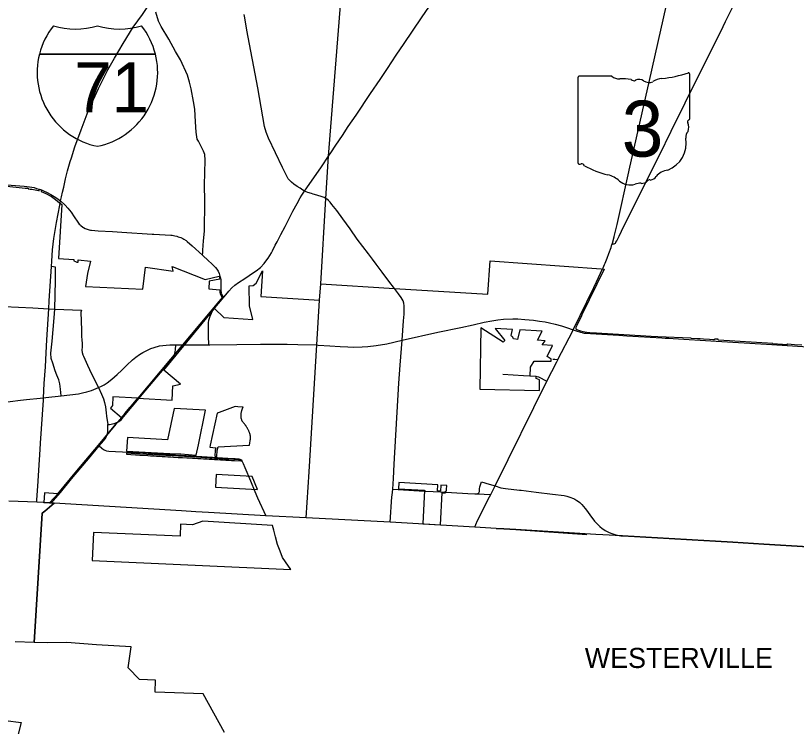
# Model space of a CAD drawing. Extents: x 1729596 to 1925846, y 659247 to 911751.
# Drawn here: x 1836127 to 1855559, y 772373 to 790063 of the extents above; entities that cross this region are included whole.
import ezdxf

# ---------------------------------------------------------------- set-up
doc = ezdxf.new("R2010")
doc.units = 0
for name, color, linetype in [('GM_X_City_Street', 7, 'Continuous'), ('GM_X_Corporation', 7, 'Continuous'), ('GM_X_Corporation_Text', 7, 'Continuous'), ('GM_X_County', 7, 'Continuous'), ('GM_X_County_Road', 7, 'Continuous'), ('GM_X_Interstate_Route', 7, 'Continuous'), ('GM_X_Interstate_Shield', 7, 'Continuous'), ('GM_X_State_Route', 7, 'Continuous'), ('GM_X_State_Shield', 7, 'Continuous'), ('GM_X_Township', 7, 'Continuous'), ('GM_X_Township_Road', 7, 'Continuous')]:
    doc.layers.add(name, color=color, linetype=linetype)

msp = doc.modelspace()

# ---------------------------------------------------------------- linework, layer by layer
at = {"layer": 'GM_X_City_Street'}
for points in [[(1845795, 782632), (1845801, 782714), (1845799, 782843), (1845789, 782905), (1845769, 782961), (1845719, 783045), (1845654, 783136), (1845556, 783268), (1845531, 783302)], [(1835705, 782831), (1835839, 782824), (1836553, 782786), (1836955, 782764), (1837100, 782758), (1837765, 782732)], [(1837765, 782732), (1837753, 782682), (1837765, 782232), (1837770, 782095)], [(1840933, 781871), (1840926, 782090), (1840925, 782331), (1840928, 782415), (1840938, 782483), (1840967, 782584), (1840998, 782659), (1841047, 782741), (1841072, 782775)], [(1845750, 781984), (1845750, 781984), (1845784, 782465), (1845795, 782632)], [(1845750, 781984), (1846636, 782185), (1847206, 782302), (1847513, 782368), (1847786, 782434), (1847977, 782469), (1848131, 782490), (1848273, 782507), (1848502, 782514), (1848624, 782515), (1848801, 782501), (1849017, 782481), (1849162, 782462), (1849304, 782438), (1849411, 782418), (1849555, 782383), (1849710, 782340), (1849838, 782298), (1850003, 782242)], [(1850003, 782242), (1850074, 782221), (1850183, 782185), (1850228, 782173), (1850245, 782170), (1850281, 782163), (1850312, 782159), (1850325, 782158), (1850431, 782150), (1850574, 782141), (1851143, 782107), (1851335, 782095)], [(1837770, 782095), (1837775, 781981), (1837783, 781922), (1837779, 781819), (1837777, 781733), (1837782, 781676), (1837802, 781618), (1837814, 781583), (1837912, 781362), (1838015, 781147), (1838193, 780805)], [(1843653, 781863), (1843947, 781841), (1844201, 781827), (1844395, 781817), (1844535, 781814), (1844750, 781817), (1844893, 781827), (1845099, 781849), (1845367, 781896), (1845750, 781984)], [(1845701, 781367), (1845750, 781984)], [(1851335, 782095), (1852214, 782040)], [(1852214, 782040), (1852297, 782035), (1852381, 782031), (1852490, 782023), (1853564, 781958), (1854813, 781882), (1856233, 781796), (1856759, 781767), (1857122, 781742)], [(1837262, 780598), (1837472, 780623), (1837692, 780652), (1837788, 780671), (1837899, 780697), (1838012, 780736), (1838193, 780805), (1838267, 780838), (1838327, 780874), (1838407, 780927), (1838522, 781011), (1838653, 781132), (1838768, 781235), (1838897, 781361), (1839033, 781492), (1839117, 781565), (1839207, 781627), (1839292, 781682), (1839379, 781723), (1839494, 781774), (1839571, 781804), (1839711, 781841), (1839792, 781854), (1839873, 781862), (1839966, 781866), (1840114, 781870)], [(1840090, 781659), (1840100, 781698), (1840105, 781743), (1840114, 781870)], [(1840114, 781870), (1840114, 781870), (1840273, 781870)], [(1840378, 781870), (1840933, 781871), (1840960, 781871)], [(1840960, 781871), (1841634, 781878), (1842225, 781888), (1842619, 781888), (1842884, 781888), (1843152, 781878), (1843626, 781866), (1843653, 781863)], [(1843361, 777564), (1843430, 778709), (1843626, 781866)], [(1849499, 781514), (1849547, 781511), (1849624, 781505)], [(1845497, 778125), (1845512, 778280), (1845535, 778545), (1845550, 778898), (1845665, 780916), (1845701, 781367)], [(1849078, 781088), (1849139, 781069), (1849352, 780964)], [(1838193, 780805), (1838268, 780643), (1838314, 780527), (1838341, 780436), (1838361, 780322), (1838379, 780175), (1838390, 780094), (1838419, 779886)], [(1838675, 779950), (1838679, 779951), (1838721, 779977), (1838758, 780012), (1838814, 780076), (1839202, 780542)], [(1838398, 779616), (1838413, 779659), (1838423, 779716), (1838425, 779769), (1838424, 779828), (1838419, 779886)], [(1838419, 779886), (1838461, 779889), (1838582, 779913), (1838619, 779924), (1838675, 779950)], [(1837662, 778703), (1837938, 779032), (1838207, 779353), (1838312, 779478), (1838354, 779530), (1838378, 779568), (1838391, 779594), (1838398, 779616)], [(1838207, 779353), (1838276, 779296), (1838316, 779268), (1838343, 779249), (1838391, 779233), (1838445, 779226), (1839292, 779180), (1840238, 779123), (1841028, 779074), (1841530, 779043), (1841590, 779040), (1841681, 779032), (1841706, 779026), (1841723, 779017), (1841743, 779001)], [(1841743, 779001), (1841743, 779001), (1841760, 778978), (1841792, 778916), (1841834, 778818), (1841974, 778482)], [(1837011, 777935), (1837067, 777991), (1837241, 778192), (1837519, 778532), (1837662, 778703)], [(1846702, 778207), (1847381, 778168), (1847556, 778157), (1847623, 778159), (1847653, 778187), (1847668, 778222), (1847673, 778281), (1847683, 778338), (1847722, 778457)], [(1847722, 778457), (1847915, 778403), (1848062, 778361)], [(1845512, 778280), (1846301, 778231), (1846340, 778229)], [(1848062, 778361), (1848204, 778314), (1848323, 778297), (1848668, 778252), (1848705, 778248)], [(1842083, 778219), (1842149, 778061), (1842358, 777614)], [(1845449, 777453), (1845493, 778084), (1845497, 778125)], [(1847623, 778159), (1847953, 778140)], [(1848705, 778248), (1849085, 778201), (1849491, 778152), (1849783, 778117), (1849847, 778104), (1849922, 778081), (1850012, 778044), (1850046, 778026), (1850094, 777998), (1850140, 777966), (1850171, 777942), (1850219, 777897), (1850262, 777849), (1850300, 777796), (1850362, 777718), (1850435, 777616), (1850491, 777539), (1850536, 777481), (1850600, 777410), (1850669, 777346), (1850724, 777300), (1850767, 777270), (1850802, 777249), (1850896, 777202), (1850967, 777174), (1851065, 777144), (1851193, 777116), (1851228, 777114), (1851242, 777113)], [(1848085, 777300), (1848276, 777289), (1848580, 777271), (1850345, 777150)], [(1851242, 777113), (1853977, 776957), (1854746, 776908), (1855849, 776844), (1860837, 776510)]]:
    msp.add_lwpolyline(points, dxfattribs=at)
at = {"layer": 'GM_X_Corporation'}
for points in [[(1835905, 785817), (1836363, 785772), (1836439, 785767), (1836438, 785752), (1836485, 785747), (1836530, 785742), (1836571, 785735), (1836613, 785728), (1836656, 785718), (1836693, 785710), (1836710, 785705), (1836712, 785746), (1836743, 785733), (1836768, 785721), (1836766, 785689), (1836880, 785635), (1837022, 785558), (1837123, 785488), (1837222, 785404), (1837273, 785365), (1837194, 784015), (1837577, 783991), (1837574, 783956), (1837620, 783941), (1837650, 783930), (1837681, 783927), (1837687, 783984), (1837990, 783954), (1837918, 783644), (1837865, 783321), (1839293, 783253), (1839358, 783800), (1840047, 783704), (1840026, 783821), (1840842, 783494), (1841189, 783579), (1841206, 783505), (1840944, 783454), (1840934, 783259), (1841208, 783235), (1841210, 783181), (1841220, 783138), (1841242, 783087), (1841269, 783047), (1841184, 782945), (1840280, 781871), (1839165, 780541), (1838544, 780578), (1838538, 780363), (1838485, 780296), (1838765, 780060), (1838745, 780037), (1838742, 780031), (1838725, 780013), (1838668, 779945), (1838625, 779894), (1838186, 779371), (1837650, 778732), (1837174, 778163), (1836848, 778182), (1836833, 777945), (1836973, 777937), (1837085, 777931), (1836852, 777733), (1836789, 777680), (1836587, 774459), (1836117, 774478)], [(1841326, 772218), (1840796, 773182), (1839597, 773227), (1839608, 773527), (1839213, 773542), (1838929, 773828), (1839006, 774350), (1838141, 774402), (1837403, 774461), (1836916, 774455), (1836587, 774459), (1836789, 777680), (1836852, 777733), (1837085, 777931), (1836973, 777937), (1836974, 777938), (1837086, 778057), (1837174, 778163), (1837650, 778732), (1838186, 779371), (1838625, 779894), (1838668, 779945), (1838725, 780013), (1838742, 780031), (1838745, 780037), (1838765, 780060), (1838767, 780058), (1838846, 780153), (1838843, 780156), (1838968, 780306), (1838971, 780303), (1839170, 780540), (1840019, 780491), (1840040, 780852), (1840233, 780886), (1839815, 781235), (1841073, 782777), (1841309, 782546), (1842031, 782501), (1841945, 782843), (1841941, 783336), (1842037, 783342), (1842114, 783400), (1842268, 783711), (1842228, 783073), (1843694, 782979), (1843719, 783387), (1845556, 783268), (1847880, 783128), (1847941, 783961), (1850704, 783760), (1850771, 783756), (1850223, 782617), (1850199, 782567), (1850139, 782444), (1850095, 782354), (1850085, 782333), (1850074, 782313), (1850069, 782299), (1850068, 782279), (1850071, 782269), (1850095, 782252), (1850134, 782235), (1850187, 782215), (1850218, 782207), (1850250, 782200), (1850345, 782187), (1850498, 782169), (1850510, 782168), (1850585, 782164), (1851810, 782096), (1851944, 782088), (1852113, 782080), (1852935, 782042), (1852934, 782037), (1853098, 782027), (1853168, 782023), (1853247, 782018), (1853247, 782016), (1853395, 782006), (1853479, 782000), (1853492, 781999), (1853509, 781998), (1853511, 781998), (1853514, 781999), (1853517, 782000), (1853519, 782001), (1853521, 782002), (1853522, 782003), (1853524, 782005), (1853526, 782007), (1853527, 782010), (1853528, 782013), (1853529, 782016), (1853529, 782020), (1853603, 782018), (1853603, 782011), (1853603, 782008), (1853604, 782004), (1853605, 782001), (1853607, 781999), (1853608, 781997), (1853610, 781995), (1853614, 781993), (1853615, 781992), (1853618, 781992), (1853621, 781991), (1854969, 781911), (1854968, 781901), (1855339, 781880), (1855340, 781890), (1855349, 781890), (1855515, 781881), (1855693, 781873)], [(1835872, 772517), (1836265, 772469), (1836073, 771716)]]:
    msp.add_lwpolyline(points, dxfattribs=at)
for points in [[(1847680, 780763), (1849165, 780736), (1849163, 781002), (1849082, 781034), (1849083, 781084), (1848937, 781088), (1848942, 781314), (1849029, 781462), (1849454, 781459), (1849454, 781517), (1849430, 781526), (1849356, 781577), (1849486, 781850), (1849232, 781869), (1849306, 781970), (1849115, 781988), (1849235, 782207), (1848677, 782244), (1848617, 782001), (1848528, 782020), (1848519, 782020), (1848515, 782021), (1848510, 782031), (1848500, 782057), (1848482, 782077), (1848469, 782087), (1848458, 782099), (1848494, 782247), (1848066, 782273), (1848300, 781976), (1848262, 781937), (1847707, 782296)], [(1838890, 779225), (1839969, 779163), (1839969, 779168), (1840239, 779153), (1840620, 779123), (1840675, 779380), (1840855, 780239), (1840069, 780286), (1839907, 779506), (1838909, 779563)], [(1840970, 779369), (1840959, 779320), (1841110, 779309), (1841096, 779248), (1841087, 779095), (1841138, 779092), (1841146, 779243), (1841165, 779331), (1841942, 779371), (1841944, 779376), (1841948, 779388), (1841951, 779398), (1841955, 779413), (1841955, 779414), (1841958, 779426), (1841959, 779436), (1841960, 779440), (1841966, 779468), (1841967, 779474), (1841967, 779484), (1841968, 779496), (1841968, 779507), (1841969, 779514), (1841970, 779522), (1841971, 779532), (1841971, 779535), (1841971, 779551), (1841970, 779593), (1841970, 779603), (1841968, 779613), (1841966, 779626), (1841964, 779635), (1841962, 779639), (1841955, 779659), (1841950, 779678), (1841946, 779691), (1841939, 779707), (1841934, 779717), (1841932, 779723), (1841928, 779732), (1841922, 779745), (1841916, 779757), (1841900, 779787), (1841897, 779793), (1841890, 779804), (1841884, 779814), (1841866, 779846), (1841864, 779849), (1841859, 779856), (1841855, 779862), (1841851, 779865), (1841847, 779870), (1841844, 779872), (1841835, 779883), (1841831, 779888), (1841820, 779903), (1841814, 779910), (1841809, 779917), (1841798, 779927), (1841797, 779929), (1841790, 779938), (1841782, 779950), (1841776, 779959), (1841773, 779964), (1841771, 779969), (1841769, 779972), (1841768, 779975), (1841761, 779987), (1841759, 779993), (1841756, 780002), (1841754, 780006), (1841749, 780017), (1841747, 780021), (1841745, 780025), (1841745, 780027), (1841742, 780036), (1841742, 780044), (1841740, 780055), (1841740, 780061), (1841740, 780063), (1841740, 780070), (1841738, 780090), (1841738, 780093), (1841738, 780099), (1841739, 780112), (1841740, 780136), (1841740, 780140), (1841741, 780150), (1841743, 780164), (1841744, 780176), (1841748, 780194), (1841749, 780200), (1841752, 780208), (1841752, 780210), (1841756, 780227), (1841761, 780247), (1841762, 780250), (1841764, 780257), (1841766, 780263), (1841768, 780271), (1841770, 780276), (1841772, 780283), (1841774, 780288), (1841777, 780293), (1841779, 780298), (1841783, 780304), (1841785, 780307), (1841788, 780313), (1841789, 780316), (1841792, 780320), (1841659, 780327), (1841589, 780331), (1841190, 780184), (1841140, 780165)], [(1838888, 779170), (1838887, 779146), (1839222, 779126), (1839417, 779112), (1839487, 779108), (1839562, 779104), (1839637, 779100), (1839707, 779096), (1839777, 779092), (1839847, 779088), (1839917, 779084), (1839987, 779080), (1840057, 779076), (1840172, 779069), (1840174, 779069), (1840277, 779063), (1840280, 779063), (1840386, 779057), (1840456, 779053), (1840526, 779049), (1840595, 779045), (1840665, 779041), (1840735, 779037), (1840805, 779033), (1840874, 779029), (1840944, 779025), (1841014, 779021), (1841079, 779018), (1841081, 779017), (1841083, 779017), (1841153, 779013), (1841156, 779013), (1841158, 779013), (1841223, 779009), (1841292, 779006), (1841362, 779002), (1841432, 778998), (1841501, 778994), (1841571, 778990), (1841732, 778980), (1841765, 778979), (1841755, 779000), (1841675, 779005), (1841439, 779020), (1841311, 779027), (1841080, 779042), (1840617, 779071), (1840183, 779097), (1839224, 779152)], [(1841118, 778645), (1841099, 778328), (1842145, 778266), (1842016, 778588)], [(1846859, 778368), (1846710, 778378), (1846702, 778229), (1846625, 778234), (1846634, 778383), (1845663, 778439), (1845654, 778289), (1846303, 778254), (1846258, 777411), (1846699, 777386), (1846740, 778185), (1846816, 778181), (1846819, 778221), (1846824, 778221), (1846830, 778222), (1846834, 778223), (1846838, 778226), (1846842, 778229), (1846846, 778234), (1846848, 778239), (1846850, 778244), (1846851, 778248), (1846852, 778267)], [(1838033, 776502), (1842974, 776280), (1842842, 776467), (1842767, 776576), (1842710, 776732), (1842648, 776896), (1842594, 777087), (1842556, 777259), (1842523, 777374), (1840783, 777481), (1840533, 777392), (1840233, 777406), (1840220, 777106), (1838064, 777201)]]:
    msp.add_lwpolyline(points, close=True, dxfattribs=at)
at = {"layer": 'GM_X_County'}
msp.add_lwpolyline([(1855849, 776844), (1854746, 776908), (1853977, 776957), (1851228, 777114), (1851193, 777116), (1850903, 777132), (1850744, 777141), (1850569, 777151), (1848580, 777271), (1848276, 777289), (1848085, 777300), (1847560, 777333), (1845449, 777453), (1843361, 777564), (1842358, 777614), (1840924, 777694), (1840611, 777712), (1840257, 777736), (1837085, 777931), (1837011, 777935), (1836973, 777937), (1836651, 777955), (1835956, 777979)], dxfattribs=at)
at = {"layer": 'GM_X_County_Road'}
for points in [[(1851209, 784694), (1851326, 784936), (1852148, 786590), (1852443, 787187), (1853141, 788601), (1853675, 789667), (1853798, 789914), (1853979, 790280), (1854272, 790859), (1854392, 791103), (1854649, 791581), (1855260, 792799), (1855898, 794041), (1856273, 794777), (1856673, 795566), (1856869, 795971), (1857028, 796294)], [(1843969, 786645), (1844100, 786841), (1844260, 787083), (1844407, 787305), (1844600, 787588), (1844962, 788122), (1845200, 788475), (1845400, 788775), (1845475, 788889), (1845613, 789100), (1845780, 789348), (1846245, 790032), (1846408, 790272)], [(1843318, 785694), (1843279, 785722), (1843205, 785766), (1843131, 785811), (1843049, 785869), (1842990, 785919), (1842913, 786003), (1842770, 786283), (1842422, 787009), (1842359, 787165), (1842321, 787304), (1842151, 788263), (1841879, 789699), (1841828, 790004), (1841819, 790093)], [(1842589, 784346), (1842634, 784434), (1842728, 784617), (1842832, 784814), (1843028, 785192), (1843132, 785389), (1843208, 785531), (1843250, 785597), (1843318, 785694), (1843374, 785774), (1843742, 786301), (1843918, 786568), (1843969, 786645)], [(1830137, 786102), (1830408, 786127), (1830473, 786131), (1830595, 786143), (1830674, 786150), (1830727, 786150), (1830805, 786149), (1831205, 786125), (1831840, 786089), (1832575, 786043), (1833895, 785967), (1834638, 785924), (1835200, 785890), (1836012, 785840), (1836343, 785821), (1836473, 785802), (1836589, 785781), (1836648, 785764), (1836710, 785745), (1836767, 785724)], [(1836767, 785724), (1836786, 785717), (1836824, 785700)], [(1836824, 785700), (1836909, 785663), (1837004, 785613), (1837124, 785539), (1837243, 785449), (1837357, 785344), (1837425, 785273), (1837506, 785171), (1837585, 785055), (1837672, 784921), (1837711, 784875), (1837731, 784855), (1837753, 784836), (1837800, 784801), (1837815, 784791), (1837856, 784768), (1837907, 784747), (1837933, 784738), (1837960, 784731), (1837988, 784725), (1838015, 784721), (1838179, 784709), (1838542, 784687), (1838768, 784673), (1839525, 784627), (1839566, 784625), (1839988, 784599), (1840024, 784595), (1840057, 784590), (1840091, 784584), (1840142, 784571), (1840175, 784561), (1840207, 784550), (1840239, 784537), (1840288, 784514), (1840316, 784498), (1840369, 784463), (1840394, 784443), (1840518, 784334), (1840776, 784103), (1840930, 783961), (1841001, 783894), (1841068, 783830), (1841103, 783792), (1841135, 783749), (1841164, 783700), (1841192, 783642), (1841213, 783581), (1841227, 783525), (1841231, 783496), (1841234, 783467), (1841236, 783438), (1841235, 783218), (1841240, 783168), (1841245, 783146), (1841249, 783135), (1841259, 783112), (1841275, 783087), (1841308, 783054)], [(1843915, 785461), (1843910, 785466), (1843876, 785495), (1843850, 785510), (1843805, 785538), (1843756, 785553), (1843625, 785594), (1843533, 785620), (1843488, 785634), (1843403, 785662), (1843358, 785678), (1843318, 785694)], [(1845531, 783302), (1845441, 783422), (1845252, 783676), (1845103, 783878), (1845012, 784005), (1844911, 784131), (1844769, 784320), (1844631, 784501), (1844451, 784757), (1844268, 785009), (1844121, 785212), (1843999, 785361), (1843954, 785418), (1843915, 785461)], [(1850968, 784364), (1851009, 784379), (1851023, 784383), (1851040, 784392), (1851054, 784403), (1851062, 784412), (1851069, 784422), (1851092, 784460), (1851118, 784507), (1851150, 784573), (1851209, 784694)], [(1842518, 784205), (1842589, 784346)], [(1841308, 783054), (1841360, 783114), (1841434, 783206), (1841511, 783291), (1841584, 783354), (1841672, 783417), (1841829, 783524), (1842048, 783668), (1842113, 783713), (1842218, 783797), (1842316, 783897), (1842383, 783983), (1842415, 784029), (1842495, 784159), (1842518, 784205)], [(1841072, 782775), (1841086, 782794), (1841225, 782955), (1841308, 783054)], [(1840273, 781870), (1840318, 781870), (1840378, 781870)], [(1840053, 781560), (1840062, 781581), (1840072, 781607), (1840088, 781652), (1840090, 781659)], [(1839781, 781234), (1839795, 781251), (1839953, 781436), (1840049, 781552), (1840053, 781560)], [(1839202, 780542), (1839276, 780630), (1839733, 781176), (1839781, 781234)]]:
    msp.add_lwpolyline(points, dxfattribs=at)
at = {"layer": 'GM_X_Interstate_Route'}
for points in [[(1837487, 786429), (1837514, 786520), (1837601, 786793), (1837756, 787221), (1837932, 787687), (1838187, 788245), (1838424, 788716), (1838589, 789007), (1838800, 789367), (1839053, 789775), (1839282, 790094), (1839487, 790389), (1839554, 790475), (1839800, 790800), (1840096, 791202), (1840599, 791880), (1841473, 793063), (1842402, 794310), (1842953, 795035), (1844609, 797255), (1845106, 797922), (1845407, 798332)], [(1837267, 785553), (1837294, 785668), (1837323, 785796), (1837371, 786001), (1837421, 786203), (1837487, 786429)], [(1837223, 785347), (1837233, 785398), (1837243, 785449), (1837267, 785553)], [(1837020, 783821), (1837027, 783953), (1837045, 784237), (1837075, 784514), (1837141, 784917), (1837223, 785347)], [(1836817, 780494), (1836820, 780550), (1836840, 780909), (1836868, 781322), (1836890, 781668), (1836906, 781995), (1836955, 782764), (1836962, 782965), (1837020, 783821)], [(1836705, 778752), (1836739, 779265), (1836749, 779422), (1836817, 780494)], [(1836655, 778007), (1836686, 778478), (1836705, 778752)], [(1836651, 777955), (1836655, 778007)]]:
    msp.add_lwpolyline(points, dxfattribs=at)
at = {"layer": 'GM_X_Interstate_Shield'}
for p, q in [((1836721, 789106), (1839606, 789106)), ((1839606, 789106), (1836721, 789106)), ((1839606, 789106), (1836721, 789106)), ((1836721, 789106), (1839606, 789106)), ((1839606, 789106), (1836721, 789106)), ((1839606, 789106), (1836721, 789106))]:
    msp.add_line(p, q, dxfattribs=at)
for centre, start, end in [((1838538, 788647), 141.669, 165.8066), ((1838538, 788647), 141.669, 165.8066), ((1837615, 791603), 253.0091, 286.9909), ((1837615, 791603), 253.0091, 286.9909), ((1838711, 791603), 253.0091, 286.9909), ((1838711, 791603), 253.0091, 286.9909), ((1837788, 788647), 14.1934, 38.331), ((1837788, 788647), 14.1934, 38.331), ((1838538, 788647), 165.8066, 258.463), ((1838538, 788647), 165.8066, 258.463), ((1837788, 788647), 281.537, 14.1934), ((1837788, 788647), 281.537, 14.1934)]:
    msp.add_arc(centre, 1875, start, end, dxfattribs=at)
at = {"layer": 'GM_X_State_Route'}
for points in [[(1851027, 784561), (1851027, 784562), (1851101, 784861), (1851390, 786171), (1851399, 786214), (1851899, 788445), (1852470, 790966), (1852613, 791609), (1852746, 792202), (1852871, 792760), (1853072, 793659), (1853214, 794287), (1853225, 794338)], [(1850785, 783867), (1850801, 783904), (1850850, 784024), (1850893, 784139), (1850946, 784292), (1850968, 784364), (1850980, 784401), (1851027, 784561)], [(1837100, 782758), (1837122, 783468), (1837121, 783747), (1837119, 783802), (1837020, 783821)], [(1850584, 783434), (1850737, 783758), (1850741, 783767), (1850750, 783788), (1850785, 783867)], [(1850003, 782242), (1850516, 783296), (1850578, 783422), (1850584, 783434)], [(1837005, 781660), (1837033, 781960), (1837087, 782544), (1837100, 782758)], [(1849593, 781442), (1849619, 781493), (1849624, 781505), (1849991, 782220), (1850003, 782242)], [(1837262, 780598), (1837243, 780763), (1837224, 780898), (1837199, 780995), (1837156, 781115), (1837115, 781226), (1837051, 781415), (1837014, 781532), (1837005, 781660)], [(1847923, 778082), (1847953, 778140), (1848062, 778361), (1849352, 780964), (1849593, 781442)], [(1836397, 780507), (1836740, 780542), (1836820, 780550), (1836877, 780557), (1837262, 780598)], [(1835722, 780425), (1836249, 780492), (1836397, 780507)], [(1847560, 777333), (1847581, 777396), (1847623, 777500), (1847923, 778082)]]:
    msp.add_lwpolyline(points, dxfattribs=at)
at = {"layer": 'GM_X_State_Shield'}
for p, q in [((1852904, 787501), (1852904, 788607)), ((1852904, 787501), (1852904, 788607)), ((1850120, 788518), (1850120, 786405)), ((1850120, 788518), (1850120, 786405)), ((1850963, 788554), (1850147, 788554)), ((1850963, 788554), (1850147, 788554)), ((1852904, 787501), (1852904, 787501)), ((1852904, 787501), (1852904, 787501))]:
    msp.add_line(p, q, dxfattribs=at)
for centre, radius, start, end in [((1851913, 791435), 2953, 275.8445, 288.9065), ((1851913, 791435), 2953, 275.8445, 288.9065), ((1852873, 788611), 31, 351.8621, 97.738), ((1852873, 788611), 31, 351.8621, 97.738), ((1850152, 788522), 32.3, 98.1301, 188.1301), ((1850152, 788522), 32.3, 98.1301, 188.1301), ((1851157, 788800), 313, 231.6195, 271.1119), ((1851157, 788800), 313, 231.6195, 271.1119), ((1851261, 787368), 1123, 80.4867, 94.9883), ((1851261, 787368), 1123, 80.4867, 94.9883), ((1851516, 788533), 90.3, 219.7921, 297.1024), ((1851516, 788533), 90.3, 219.7921, 297.1024), ((1851648, 788289), 188, 54.4667, 119.1411), ((1851648, 788289), 188, 54.4667, 119.1411), ((1851890, 788624), 226, 233.8562, 294.8282), ((1851890, 788624), 226, 233.8562, 294.8282), ((1852289, 787909), 594, 97.3462, 120.7689), ((1852289, 787909), 594, 97.3462, 120.7689), ((1852897, 787420), 48, 107.944, 210.337), ((1852897, 787420), 48, 107.944, 210.337), ((1852592, 787280), 288, 340.033, 23.6496), ((1852592, 787280), 288, 340.033, 23.6496), ((1852871, 787497), 33.2, 289.6038, 7.7341), ((1852871, 787497), 33.2, 289.6038, 7.7341), ((1852078, 786898), 739, 292.3089, 8.9858), ((1852078, 786898), 739, 292.3089, 8.9858), ((1853015, 787039), 210, 136.8065, 186.9296), ((1853015, 787039), 210, 136.8065, 186.9296), ((1850152, 786400), 32.5, 171.9584, 258.3066), ((1850152, 786400), 32.5, 171.9584, 258.3066), ((1850157, 786616), 248, 267.339, 280.6039), ((1850157, 786616), 248, 267.339, 280.6039), ((1850208, 786283), 89.5, 29.7484, 93.2717), ((1850208, 786283), 89.5, 29.7484, 93.2717), ((1851338, 788181), 2132, 240.4129, 257.1985), ((1851338, 788181), 2132, 240.4129, 257.1985), ((1850703, 785455), 667, 47.1842, 75.836), ((1850703, 785455), 667, 47.1842, 75.836), ((1851877, 786200), 239, 282.8732, 323.2771), ((1851877, 786200), 239, 282.8732, 323.2771), ((1852389, 785811), 404, 94.4031, 142.5768), ((1852389, 785811), 404, 94.4031, 142.5768), ((1851424, 786272), 423, 230.7004, 286.2918), ((1851424, 786272), 423, 230.7004, 286.2918), ((1851669, 785542), 348, 85.6951, 111.2099), ((1851669, 785542), 348, 85.6951, 111.2099), ((1851700, 786114), 226, 268.777, 315.5493), ((1851700, 786114), 226, 268.777, 315.5493), ((1851904, 785909), 63.5, 65.7517, 132.6484), ((1851904, 785909), 63.5, 65.7517, 132.6484)]:
    msp.add_arc(centre, radius, start, end, dxfattribs=at)
at = {"layer": 'GM_X_Township'}
msp.add_lwpolyline([(1843361, 777564), (1843430, 778709), (1843626, 781866), (1843694, 782979), (1843719, 783387), (1843850, 785510), (1843918, 786568), (1844278, 791160)], dxfattribs=at)
at = {"layer": 'GM_X_Township_Road'}
for points in [[(1840776, 784103), (1840783, 784165), (1840786, 784226), (1840804, 784460), (1840825, 784699), (1840840, 785445), (1840831, 785855), (1840833, 786147), (1840842, 786466), (1840835, 786609), (1840806, 786690), (1840723, 786857), (1840679, 786939), (1840648, 786992), (1840620, 787160), (1840605, 787423), (1840587, 787735), (1840557, 787925), (1840498, 788237), (1840457, 788405), (1840405, 788583), (1840228, 788959), (1840110, 789170), (1839941, 789478), (1839747, 789795), (1839679, 789921), (1839616, 790145)], [(1848256, 781141), (1848764, 781105), (1849078, 781088)], [(1841974, 778482), (1842083, 778219)], [(1846340, 778229), (1846702, 778207)]]:
    msp.add_lwpolyline(points, dxfattribs=at)

# ---------------------------------------------------------------- texts
at = {"layer": 'GM_X_Corporation_Text'}
msp.add_text('WESTERVILLE', height=500, rotation=0, dxfattribs=at).set_placement((1850293, 773826))
at = {"layer": 'GM_X_Interstate_Shield'}
msp.add_text('71', height=1250, dxfattribs=at).set_placement((1837586, 787653))
msp.add_text('71', height=1250, dxfattribs=at).set_placement((1837586, 787653))
at = {"layer": 'GM_X_State_Shield'}
msp.add_text('3', height=1392, dxfattribs=at).set_placement((1851212, 786554))
msp.add_text('3', height=1392, dxfattribs=at).set_placement((1851212, 786554))

doc.saveas('drawing.dxf')
